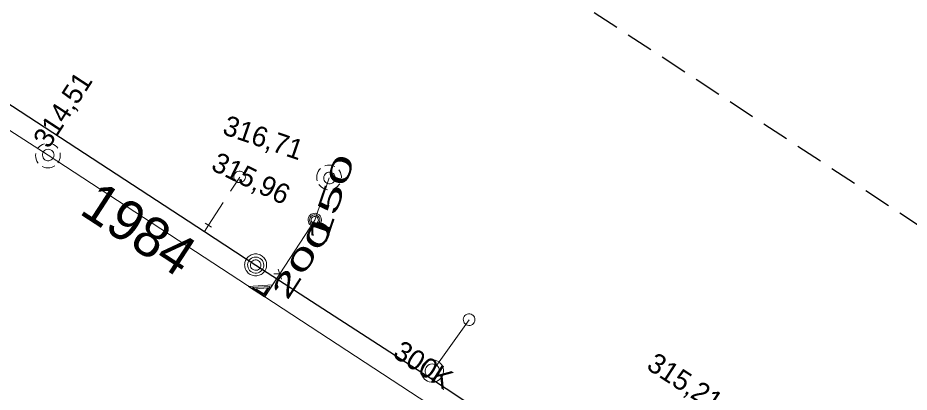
# Model space of a CAD drawing. Extents: x -742876 to -742577, y -1054710 to -1054452.
# Drawn here: x -742678.08 to -742642.52, y -1054517.81 to -1054502.89 of the extents above; entities that cross this region are included whole.
import ezdxf

# ---------------------------------------------------------------- set-up
doc = ezdxf.new("R2010")
doc.units = 0
doc.header["$LTSCALE"] = 0.36
doc.linetypes.add('MEDIUM_DASHED', pattern=[4.5, 3, -1.5])
for name, color, linetype, lineweight in [('1', 7, 'MEDIUM_DASHED', 25), ('18', 7, 'Continuous', 13), ('20', 7, 'Continuous', 13), ('49', 7, 'Continuous', 13), ('8', 7, 'Continuous', 13)]:
    doc.layers.add(name, color=color, linetype=linetype, lineweight=lineweight)

msp = doc.modelspace()

# ---------------------------------------------------------------- linework, layer by layer
at = {"layer": '1'}
msp.add_lwpolyline([(-742732.306, -1054452.031), (-742576.984, -1054553.898), (-742576.983, -1054553.899), (-742576.982, -1054553.901), (-742576.981, -1054553.903), (-742576.98, -1054553.905), (-742576.98, -1054553.907), (-742576.98, -1054553.909), (-742576.981, -1054553.91), (-742576.982, -1054553.912), (-742690.097, -1054710.32), (-742690.098, -1054710.321), (-742690.099, -1054710.322), (-742690.101, -1054710.323), (-742690.103, -1054710.324), (-742690.105, -1054710.324), (-742690.107, -1054710.324), (-742690.108, -1054710.323), (-742690.11, -1054710.322), (-742875.986, -1054593.411)], dxfattribs=at)
at = {"layer": '18'}
for p, q in [((-742667.424, -1054513.1), (-742667.868, -1054513.101)), ((-742667.7, -1054512.905), (-742667.567, -1054513.314))]:
    msp.add_line(p, q, dxfattribs=at)
for points in [[(-742677.023, -1054507.907), (-742677.094, -1054507.935), (-742677.161, -1054507.974), (-742677.221, -1054508.022), (-742677.272, -1054508.079), (-742677.296, -1054508.113)], [(-742676.482, -1054508.09), (-742676.532, -1054508.032), (-742676.59, -1054507.982), (-742676.655, -1054507.941), (-742676.726, -1054507.912), (-742676.775, -1054507.898)], [(-742677.368, -1054508.299), (-742677.374, -1054508.376), (-742677.369, -1054508.453), (-742677.352, -1054508.528), (-742677.323, -1054508.599), (-742677.282, -1054508.665), (-742677.267, -1054508.687)], [(-742676.487, -1054508.676), (-742676.446, -1054508.611), (-742676.415, -1054508.541), (-742676.396, -1054508.466), (-742676.388, -1054508.39), (-742676.393, -1054508.313), (-742676.399, -1054508.278)], [(-742677.11, -1054508.816), (-742677.04, -1054508.847), (-742676.965, -1054508.866), (-742676.889, -1054508.873), (-742676.812, -1054508.868), (-742676.737, -1054508.851), (-742676.665, -1054508.823), (-742676.605, -1054508.788)], [(-742665.431, -1054508.821), (-742665.502, -1054508.791), (-742665.576, -1054508.77), (-742665.653, -1054508.762), (-742665.73, -1054508.767), (-742665.805, -1054508.783), (-742665.831, -1054508.791)], [(-742666.004, -1054508.898), (-742666.056, -1054508.954), (-742666.098, -1054509.018), (-742666.13, -1054509.088), (-742666.15, -1054509.163), (-742666.158, -1054509.239), (-742666.155, -1054509.316), (-742666.141, -1054509.384)], [(-742665.172, -1054509.275), (-742665.176, -1054509.199), (-742665.191, -1054509.123), (-742665.217, -1054509.05), (-742665.254, -1054508.984), (-742665.279, -1054508.95)], [(-742666.074, -1054509.532), (-742666.026, -1054509.592), (-742665.969, -1054509.644), (-742665.905, -1054509.687), (-742665.835, -1054509.719), (-742665.761, -1054509.739), (-742665.726, -1054509.745)], [(-742665.521, -1054509.727), (-742665.45, -1054509.699), (-742665.384, -1054509.66), (-742665.324, -1054509.612), (-742665.274, -1054509.554), (-742665.244, -1054509.512)], [(-742667.637, -1054513.101), (-742668.237, -1054514.017), (-742668.881, -1054513.596), (-742667.92, -1054513.533)], [(-742668.027, -1054513.606), (-742668.254, -1054513.953), (-742668.728, -1054513.643), (-742668.026, -1054513.604)], [(-742668.112, -1054513.649), (-742668.272, -1054513.894), (-742668.583, -1054513.69), (-742668.111, -1054513.65)]]:
    msp.add_lwpolyline(points, dxfattribs=at)
for points in [[(-742676.639, -1054508.359), (-742676.645, -1054508.307), (-742676.663, -1054508.257), (-742676.691, -1054508.213), (-742676.729, -1054508.176), (-742676.774, -1054508.149), (-742676.824, -1054508.133), (-742676.876, -1054508.128), (-742676.928, -1054508.135), (-742676.977, -1054508.154), (-742677.021, -1054508.184), (-742677.056, -1054508.223), (-742677.082, -1054508.268), (-742677.097, -1054508.319), (-742677.1, -1054508.371), (-742677.092, -1054508.423), (-742677.071, -1054508.471), (-742677.041, -1054508.514), (-742677.001, -1054508.549), (-742676.955, -1054508.573), (-742676.904, -1054508.587), (-742676.852, -1054508.589), (-742676.8, -1054508.579), (-742676.752, -1054508.557), (-742676.71, -1054508.525), (-742676.677, -1054508.485), (-742676.653, -1054508.438), (-742676.641, -1054508.387)], [(-742665.725, -1054509.491), (-742665.673, -1054509.503), (-742665.62, -1054509.502), (-742665.57, -1054509.49), (-742665.522, -1054509.466), (-742665.482, -1054509.432), (-742665.451, -1054509.39), (-742665.429, -1054509.342), (-742665.419, -1054509.291), (-742665.421, -1054509.238), (-742665.435, -1054509.187), (-742665.461, -1054509.141), (-742665.495, -1054509.102), (-742665.538, -1054509.071), (-742665.586, -1054509.051), (-742665.638, -1054509.042), (-742665.69, -1054509.046), (-742665.741, -1054509.061), (-742665.787, -1054509.087), (-742665.824, -1054509.123), (-742665.854, -1054509.167), (-742665.873, -1054509.215), (-742665.88, -1054509.268), (-742665.875, -1054509.32), (-742665.859, -1054509.37), (-742665.831, -1054509.415), (-742665.795, -1054509.453), (-742665.75, -1054509.48)], [(-742665.975, -1054510.947), (-742665.98, -1054510.891), (-742665.997, -1054510.838), (-742666.026, -1054510.789), (-742666.065, -1054510.748), (-742666.11, -1054510.716), (-742666.163, -1054510.694), (-742666.218, -1054510.683), (-742666.274, -1054510.685), (-742666.328, -1054510.698), (-742666.379, -1054510.723), (-742666.424, -1054510.758), (-742666.46, -1054510.801), (-742666.485, -1054510.851), (-742666.5, -1054510.906), (-742666.502, -1054510.962), (-742666.494, -1054511.017), (-742666.473, -1054511.07), (-742666.441, -1054511.116), (-742666.401, -1054511.155), (-742666.353, -1054511.185), (-742666.301, -1054511.204), (-742666.245, -1054511.211), (-742666.188, -1054511.207), (-742666.134, -1054511.19), (-742666.085, -1054511.163), (-742666.044, -1054511.125), (-742666.011, -1054511.08), (-742665.987, -1054511.029), (-742665.975, -1054510.974)], [(-742666.034, -1054510.95), (-742666.039, -1054510.901), (-742666.058, -1054510.855), (-742666.085, -1054510.814), (-742666.122, -1054510.781), (-742666.166, -1054510.759), (-742666.215, -1054510.747), (-742666.264, -1054510.747), (-742666.311, -1054510.759), (-742666.355, -1054510.782), (-742666.392, -1054510.815), (-742666.421, -1054510.856), (-742666.438, -1054510.903), (-742666.443, -1054510.952), (-742666.436, -1054511.001), (-742666.419, -1054511.047), (-742666.391, -1054511.087), (-742666.353, -1054511.12), (-742666.309, -1054511.142), (-742666.261, -1054511.154), (-742666.212, -1054511.153), (-742666.164, -1054511.141), (-742666.12, -1054511.117), (-742666.083, -1054511.084), (-742666.056, -1054511.043), (-742666.039, -1054510.996)], [(-742666.093, -1054510.954), (-742666.098, -1054510.912), (-742666.115, -1054510.874), (-742666.144, -1054510.843), (-742666.178, -1054510.82), (-742666.218, -1054510.809), (-742666.261, -1054510.809), (-742666.301, -1054510.821), (-742666.335, -1054510.844), (-742666.362, -1054510.876), (-742666.379, -1054510.914), (-742666.384, -1054510.955), (-742666.379, -1054510.997), (-742666.36, -1054511.034), (-742666.333, -1054511.066), (-742666.296, -1054511.088), (-742666.257, -1054511.099), (-742666.215, -1054511.098), (-742666.174, -1054511.085), (-742666.141, -1054511.062), (-742666.114, -1054511.029), (-742666.098, -1054510.991)]]:
    msp.add_lwpolyline(points, close=True, dxfattribs=at)
at = {"layer": '20'}
for points in [[(-742676.87, -1054508.37), (-742698.484, -1054494.465), (-742717.239, -1054482.399)], [(-742676.87, -1054508.37), (-742698.484, -1054494.465), (-742717.239, -1054482.399)], [(-742649.41, -1054526.33), (-742652.355, -1054524.403), (-742656.992, -1054521.37), (-742668.232, -1054514.019), (-742676.87, -1054508.37)], [(-742649.41, -1054526.33), (-742652.355, -1054524.403), (-742656.992, -1054521.37), (-742668.232, -1054514.019), (-742676.87, -1054508.37)]]:
    msp.add_lwpolyline(points, dxfattribs=at)
at = {"layer": '49'}
for p, q in [((-742665.66, -1054509.27), (-742666.239, -1054510.96)), ((-742665.66, -1054509.27), (-742666.239, -1054510.96)), ((-742666.239, -1054510.96), (-742668.232, -1054514.019)), ((-742666.239, -1054510.96), (-742668.232, -1054514.019))]:
    msp.add_line(p, q, dxfattribs=at)
at = {"layer": '8'}
msp.add_line((-742670.355, -1054511.238), (-742670.609, -1054511.072), dxfattribs=at)
at = {"layer": '8', "lineweight": 25}
for points in [[(-742715.62, -1054482.05), (-742696.811, -1054494.328), (-742670.64, -1054511.411), (-742668.59, -1054512.75)], [(-742668.59, -1054512.75), (-742661.706, -1054517.203), (-742659.59, -1054518.6), (-742636.057, -1054533.803), (-742635.66, -1054534.06)]]:
    msp.add_lwpolyline(points, dxfattribs=at)
at = {"layer": '8'}
for points in [[(-742669.108, -1054509.037), (-742669.155, -1054509.014), (-742669.207, -1054509.002), (-742669.259, -1054509.001), (-742669.311, -1054509.013), (-742669.358, -1054509.036), (-742669.399, -1054509.069), (-742669.431, -1054509.11), (-742669.454, -1054509.157), (-742669.464, -1054509.209), (-742669.463, -1054509.262), (-742669.45, -1054509.312), (-742669.426, -1054509.359), (-742669.392, -1054509.399), (-742669.35, -1054509.43), (-742669.302, -1054509.452), (-742669.25, -1054509.46), (-742669.198, -1054509.459), (-742669.147, -1054509.444), (-742669.101, -1054509.419), (-742669.062, -1054509.384), (-742669.032, -1054509.341), (-742669.012, -1054509.292), (-742669.004, -1054509.24), (-742669.008, -1054509.187), (-742669.023, -1054509.138), (-742669.05, -1054509.092), (-742669.086, -1054509.054)], [(-742668.272, -1054512.747), (-742668.279, -1054512.686), (-742668.297, -1054512.626), (-742668.326, -1054512.571), (-742668.365, -1054512.523), (-742668.412, -1054512.483), (-742668.466, -1054512.453), (-742668.525, -1054512.433), (-742668.587, -1054512.426), (-742668.649, -1054512.43), (-742668.708, -1054512.446), (-742668.764, -1054512.474), (-742668.814, -1054512.511), (-742668.855, -1054512.558), (-742668.887, -1054512.611), (-742668.907, -1054512.67), (-742668.917, -1054512.731), (-742668.914, -1054512.793), (-742668.899, -1054512.853), (-742668.873, -1054512.91), (-742668.837, -1054512.96), (-742668.791, -1054513.003), (-742668.739, -1054513.035), (-742668.681, -1054513.058), (-742668.62, -1054513.068), (-742668.558, -1054513.067), (-742668.497, -1054513.054), (-742668.44, -1054513.029), (-742668.389, -1054512.994), (-742668.345, -1054512.95), (-742668.311, -1054512.898), (-742668.287, -1054512.841), (-742668.275, -1054512.78)], [(-742668.387, -1054512.747), (-742668.392, -1054512.698), (-742668.409, -1054512.651), (-742668.438, -1054512.61), (-742668.476, -1054512.577), (-742668.52, -1054512.553), (-742668.568, -1054512.541), (-742668.618, -1054512.54), (-742668.666, -1054512.552), (-742668.711, -1054512.574), (-742668.749, -1054512.607), (-742668.777, -1054512.647), (-742668.797, -1054512.694), (-742668.804, -1054512.743), (-742668.799, -1054512.793), (-742668.782, -1054512.84), (-742668.755, -1054512.882), (-742668.718, -1054512.916), (-742668.674, -1054512.94), (-742668.627, -1054512.954), (-742668.576, -1054512.955), (-742668.527, -1054512.945), (-742668.483, -1054512.923), (-742668.444, -1054512.891), (-742668.414, -1054512.852), (-742668.395, -1054512.806), (-742668.387, -1054512.756)], [(-742659.955, -1054514.731), (-742660.002, -1054514.708), (-742660.054, -1054514.696), (-742660.106, -1054514.695), (-742660.157, -1054514.707), (-742660.205, -1054514.73), (-742660.245, -1054514.763), (-742660.278, -1054514.804), (-742660.3, -1054514.852), (-742660.311, -1054514.903), (-742660.309, -1054514.957), (-742660.296, -1054515.007), (-742660.272, -1054515.053), (-742660.237, -1054515.094), (-742660.195, -1054515.124), (-742660.147, -1054515.146), (-742660.095, -1054515.154), (-742660.043, -1054515.153), (-742659.992, -1054515.138), (-742659.947, -1054515.112), (-742659.907, -1054515.077), (-742659.877, -1054515.035), (-742659.858, -1054514.985), (-742659.85, -1054514.933), (-742659.854, -1054514.881), (-742659.87, -1054514.831), (-742659.896, -1054514.785), (-742659.932, -1054514.748)], [(-742661.305, -1054516.598), (-742661.369, -1054516.564), (-742661.438, -1054516.54), (-742661.51, -1054516.528), (-742661.583, -1054516.529), (-742661.656, -1054516.54), (-742661.725, -1054516.564), (-742661.789, -1054516.598), (-742661.848, -1054516.643), (-742661.898, -1054516.696), (-742661.939, -1054516.758), (-742661.969, -1054516.824), (-742661.987, -1054516.895), (-742661.994, -1054516.967), (-742661.989, -1054517.04), (-742661.973, -1054517.112), (-742661.944, -1054517.179), (-742661.905, -1054517.241), (-742661.857, -1054517.296), (-742661.8, -1054517.343), (-742661.737, -1054517.379), (-742661.668, -1054517.404), (-742661.597, -1054517.418), (-742661.523, -1054517.421), (-742661.451, -1054517.41), (-742661.381, -1054517.389), (-742661.316, -1054517.356), (-742661.256, -1054517.313), (-742661.204, -1054517.261), (-742661.162, -1054517.201), (-742661.13, -1054517.135), (-742661.11, -1054517.065), (-742661.101, -1054516.992), (-742661.103, -1054516.919), (-742661.118, -1054516.848), (-742661.145, -1054516.779), (-742661.182, -1054516.716), (-742661.229, -1054516.66), (-742661.284, -1054516.613)], [(-742661.392, -1054516.734), (-742661.444, -1054516.707), (-742661.501, -1054516.692), (-742661.559, -1054516.688), (-742661.617, -1054516.697), (-742661.672, -1054516.716), (-742661.722, -1054516.747), (-742661.765, -1054516.787), (-742661.798, -1054516.835), (-742661.821, -1054516.889), (-742661.832, -1054516.947), (-742661.832, -1054517.005), (-742661.82, -1054517.062), (-742661.796, -1054517.115), (-742661.762, -1054517.164), (-742661.719, -1054517.203), (-742661.669, -1054517.233), (-742661.613, -1054517.253), (-742661.555, -1054517.26), (-742661.497, -1054517.255), (-742661.44, -1054517.239), (-742661.389, -1054517.212), (-742661.344, -1054517.175), (-742661.307, -1054517.129), (-742661.281, -1054517.077), (-742661.265, -1054517.021), (-742661.261, -1054516.962), (-742661.27, -1054516.904), (-742661.29, -1054516.85), (-742661.321, -1054516.8), (-742661.361, -1054516.757)]]:
    msp.add_lwpolyline(points, close=True, dxfattribs=at)
at = {"layer": '8', "linetype": 'MEDIUM_DASHED'}
msp.add_lwpolyline([(-742670.64, -1054511.411), (-742670.477, -1054511.159), (-742669.226, -1054509.237)], dxfattribs=at)
at = {"layer": '8'}
for points in [[(-742668.159, -1054512.739), (-742668.162, -1054512.694), (-742668.169, -1054512.649), (-742668.181, -1054512.604), (-742668.196, -1054512.562), (-742668.218, -1054512.521), (-742668.243, -1054512.482), (-742668.272, -1054512.447), (-742668.304, -1054512.414), (-742668.34, -1054512.386), (-742668.377, -1054512.361), (-742668.419, -1054512.34), (-742668.462, -1054512.323), (-742668.505, -1054512.311), (-742668.551, -1054512.304), (-742668.597, -1054512.302), (-742668.642, -1054512.304), (-742668.688, -1054512.311), (-742668.732, -1054512.323), (-742668.775, -1054512.34), (-742668.816, -1054512.361), (-742668.853, -1054512.386), (-742668.89, -1054512.414), (-742668.922, -1054512.447), (-742668.951, -1054512.482), (-742668.976, -1054512.521), (-742668.997, -1054512.562), (-742669.012, -1054512.604), (-742669.025, -1054512.649), (-742669.032, -1054512.694), (-742669.034, -1054512.74), (-742669.032, -1054512.785), (-742669.025, -1054512.83), (-742669.012, -1054512.875), (-742668.997, -1054512.917), (-742668.976, -1054512.958), (-742668.951, -1054512.997), (-742668.922, -1054513.032), (-742668.89, -1054513.065), (-742668.853, -1054513.093), (-742668.816, -1054513.118), (-742668.775, -1054513.139), (-742668.732, -1054513.156), (-742668.688, -1054513.167), (-742668.642, -1054513.175), (-742668.597, -1054513.177), (-742668.551, -1054513.175), (-742668.505, -1054513.167), (-742668.462, -1054513.156), (-742668.419, -1054513.139), (-742668.377, -1054513.118), (-742668.34, -1054513.093), (-742668.304, -1054513.065), (-742668.272, -1054513.032), (-742668.243, -1054512.997), (-742668.218, -1054512.958), (-742668.196, -1054512.917), (-742668.181, -1054512.875), (-742668.169, -1054512.83), (-742668.162, -1054512.785), (-742668.159, -1054512.74)], [(-742661.706, -1054517.203), (-742661.539, -1054516.98), (-742660.072, -1054514.931)]]:
    msp.add_lwpolyline(points, dxfattribs=at)

# ---------------------------------------------------------------- texts
at = {"layer": '1'}
for s, height, rotation, p in [('314,51', 0.8, 57, (-742676.852, -1054508.138)), ('316,71', 0.8, 341, (-742669.964, -1054507.51)), ('315,96', 0.8, 334, (-742670.42, -1054508.93)), ('1984', 1.6, 327, (-742675.68, -1054510.673)), ('300K', 0.8, 327, (-742663.17, -1054516.379)), ('315,21', 0.8, 327, (-742653.048, -1054516.86))]:
    msp.add_text(s, height=height, rotation=rotation, dxfattribs=at).set_placement(p)
for s, rotation, width, p in [('150 ', 71, 2.05, (-742665.812, -1054511.972)), ('200 ', 57, 1.95, (-742667.342, -1054514.192))]:
    msp.add_text(s, height=0.8, rotation=rotation, dxfattribs=dict(at, width=width)).set_placement(p)

doc.saveas('drawing.dxf')
